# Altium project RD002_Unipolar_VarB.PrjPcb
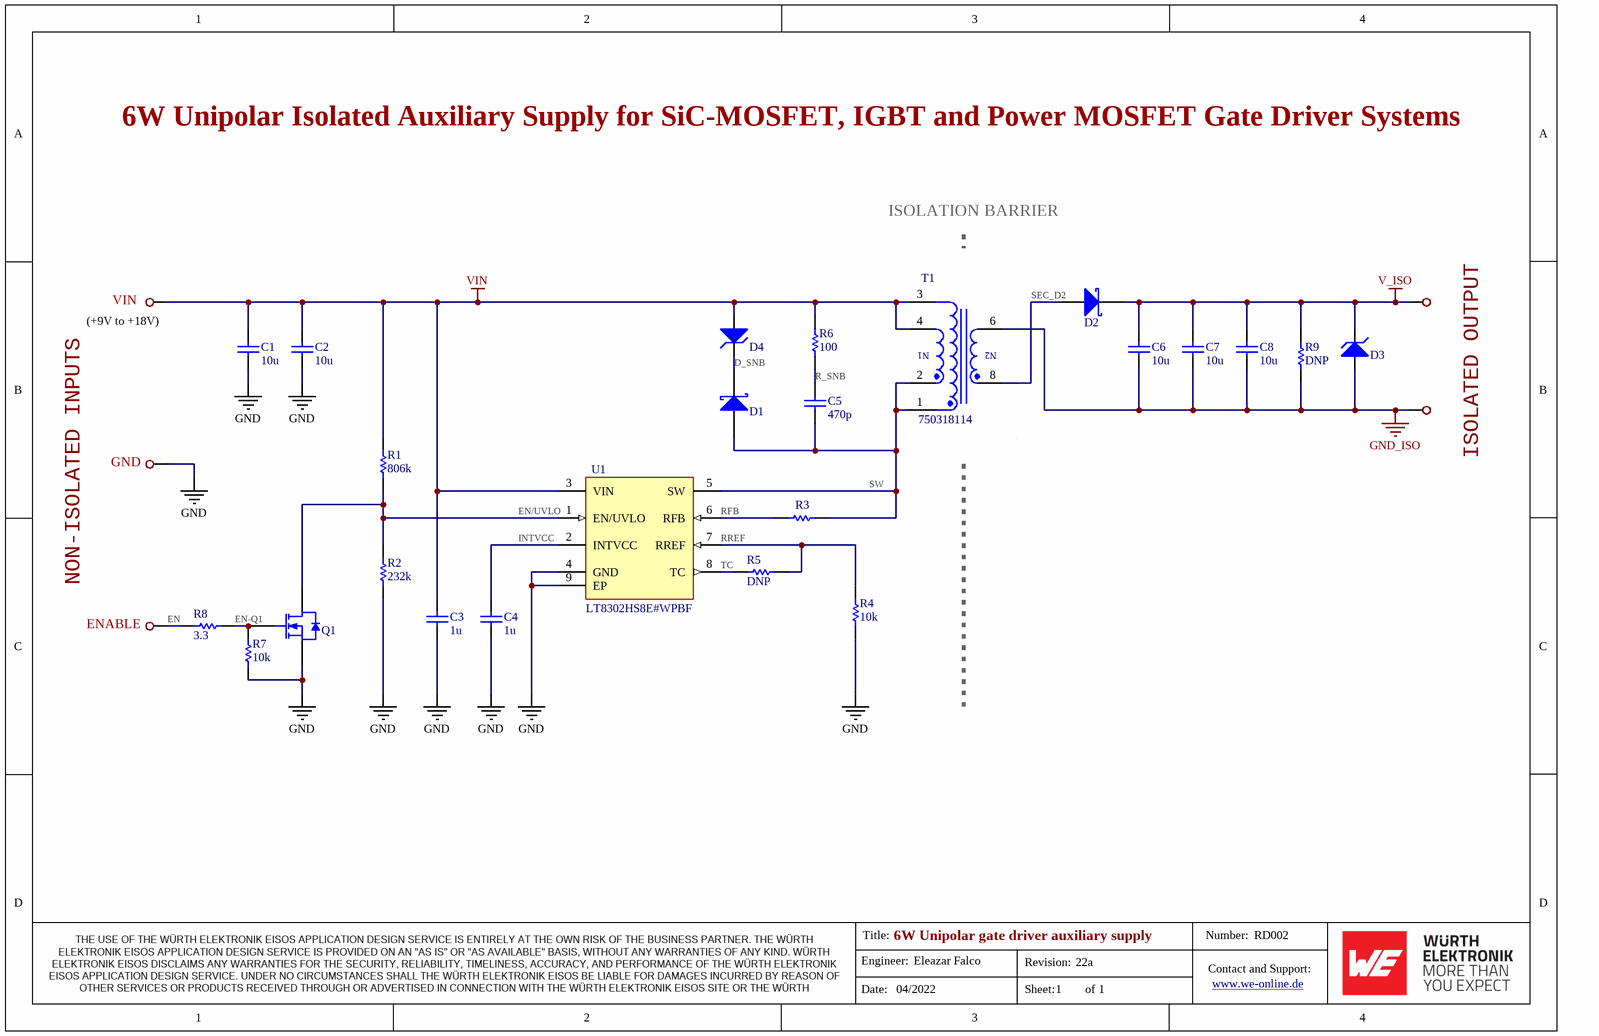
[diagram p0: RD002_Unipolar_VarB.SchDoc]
Board_Name: RD001_VarB; Engineer: Eleazar Falco; Project_Title: Isolated unipolar auxiliary supply for gate driver; Revision: 21a; Variant: N/A; Version: N/A
1 sheet, 29 parts. Net scope: global (net labels, ports and power ports of the same name join across sheets).
Board file: RD002_Unipolar_VarB.PcbDoc

## Sheet RD002_Unipolar_VarB.SchDoc: 6W Unipolar gate driver auxiliary supply
size A4; Date: 04/2022; Author: Eleazar Falco; DocumentNumber: RD002; Revision: 22a; SheetNumber: 1; SheetTotal: 1

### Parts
C1  value 10u  [C1206]  (hidden comment: 885012108022)
C2  value 10u  [C1206]  (hidden comment: 885012108022)
C3  value 1u  [C0805]  (hidden comment: 885012207103)
C4  value 1u  [C0805]  (hidden comment: 885012207103)
C5  value 470p  [C0805]  (hidden comment: 885012207084)
C6  value 10u  [C1206]  (hidden comment: 885012108022)
C7  value 10u  [C1206]  (hidden comment: 885012108022)
C8  value 10u  [C1206]  (hidden comment: 885012108022)
D1  V1PM10-M3  [D_DO-219AD_(uSMP)]  (value not drawn)
D2  VSSAF3M10-M3  [D_DO-221AC_(SMA_Slim)]  (value not drawn)
D3  PLZ16BG3H  [D_DO-219AC_(uSMF)]  (value not drawn)
D4  BZG03C27-M3  [D_DO-214AC_(SMA)]  (value not drawn)
H1  TH-1MM  [PIN-TH-ROUND-1MM]  (value not drawn)  (no BOM)
H2  TH-1MM  [PIN-TH-ROUND-1MM]  (value not drawn)  (no BOM)
H3  TH-1MM  [PIN-TH-ROUND-1MM]  (value not drawn)  (no BOM)
H4  TH-1MM  [PIN-TH-ROUND-1MM]  (value not drawn)  (no BOM)
H5  TH-1MM  [PIN-TH-ROUND-1MM]  (value not drawn)  (no BOM)
Q1  SQ2318AES-T1_BE3  [IC_SOT23-3_V]  (value not drawn)
R1  value 806k  [R0603]  (hidden comment: RC0603FR-07806KL)
R2  value 232k  [R0603]  (hidden comment: RC0603FR-07232KL)
R3  RT0603FRE0771K5L  [R0603]  (value not drawn)
R4  value 10k  [R0603]  (hidden comment: RT0603BRD0710KL)
R5  value DNP  [R0603_DNP]  (hidden comment: R0603_DNP)
R6  value 100  [R0805]  (hidden comment: CMP0805-FX-1000ELF)
R7  value 10k  [R0603]  (hidden comment: RC0603FR-0710KL)
R8  value 3.3  [R0603]  (hidden comment: RC0603FR-073R3L)
R9  value DNP  [R0603_DNP]  (hidden comment: R0603_DNP)
T1  750318114  [EP7_Extended_Rail]
U1  LT8302HS8E#WPBF  [LT-S8E-8_V]

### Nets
GND: C1.2 C2.1 C3.1 C4.1 H2.1 Q1.2(S) R2.1 R4.1 R7.1 U1.4(GND) U1.9(EP)
GND_ISO: C6.1 C7.1 C8.1 D3.A H5.1 R9.1 T1.6
V_ISO: C6.2 C7.2 C8.2 D2.C D3.C H4.1 R9.2
VIN: C1.1 C2.2 C3.2 D4.A H1.1 R1.2 R6.2 T1.3 T1.4 U1.3(VIN)
D_SNB: D1.C D4.C
EN: H3.1 R8.1
EN-Q1: Q1.1(G) R7.2 R8.2
EN/UVLO: Q1.3(D) R1.1 R2.2 U1.1(EN/UVLO)
INTVCC: C4.2 U1.2(INTVCC)
R_SNB: C5.2 R6.1
RFB: R3.1 U1.6(RFB)
RREF: R4.2 R5.2 U1.7(RREF)
SEC_D2: D2.A T1.8
SW: C5.1 D1.A R3.2 T1.1 T1.2 U1.5(SW)
TC: R5.1 U1.8(TC)

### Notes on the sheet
- 6W Unipolar Isolated Auxiliary Supply for SiC-MOSFET, IGBT and Power MOSFET Gate Driver Systems
- ISOLATION BARRIER
- (near H1) VIN
- (near H1) (+9V to +18V)
- (near H2) GND
- ISOLATED OUTPUT
- NON-ISOLATED INPUTS
- (near H3) ENABLE
- Engineer:
- Title:
- Revision:
- Number:
- Contact and Support:
- www.we-online.de <http://www.we-online.de>
- THE USE OF THE WÜRTH ELEKTRONIK EISOS APPLICATION DESIGN SERVICE IS ENTIRELY AT THE OWN RISK OF THE BUSINESS PARTNER. THE WÜRTH ELEKTRONIK EISOS APPLICATION DESIGN SERVICE IS PROVIDED ON AN "AS IS" OR "AS AVAILABLE" BASIS, WITHOUT ANY WARRANTIES OF ANY KIND. WÜRTH ELEKTRONIK EISOS DISCLAIMS ANY WARRANTIES FOR THE SECURITY, RELIABILITY, TIMELINESS, ACCURACY, AND PERFORMANCE OF THE WÜRTH ELEKTRONIK EISOS APPLICATION DESIGN SERVICE. UNDER NO CIRCUMSTANCES SHALL THE WÜRTH ELEKTRONIK EISOS BE LIABLE FOR DAMAGES INCURRED BY REASON OF OTHER SERVICES OR PRODUCTS RECEIVED THROUGH OR ADVERTISED IN CONNECTION WITH THE WÜRTH ELEKTRONIK EISOS SITE OR THE WÜRTH ELEKTRONIK EISOS APPLICATION DESIGN SERVICE.
- Date:
- Sheet:
- of

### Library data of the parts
C1 C2 C6-C8 = 885012108022: MLCC 10uF 50V 10% X7R 1206 General Purpose; MFR: Wurth Elektronik
C3 C4 = 885012207103: MLCC 1uF 50V 10% X7R 0805 General Purpose; MFR: Wurth Elektronik
C5 = 885012207084: MLCC SMD 470p 50V 10% X7R 0805 General Purpose; MFR: Wurth Elektronik
D1 = V1PM10-M3: Schottky Rectifier 1A 100V SMD DO-219AD (uSMP) V1PM10-M3; MFR: Vishay
D2 = VSSAF3M10-M3: Schottky Rectifier 3A 100V SMD DO-221AC (SMA_Slim) VSSAF3M10-M3; MFR: Vishay; Type: Schottky Barrier Rectifier Trench-MOS
D3 = PLZ16BG3H: Zener 16V 0.5W SMD DO-219AC (uSMF) PLZ16BG3H; MFR: Vishay
D4 = BZG03C27-M3: Zener 27V 3W DO-214AC (SMA) BZG03C27-M3; MFR: Vishay
H1-H5 = Pin_hole_1mm: not available; SymbolName_1: TEST-POINT-ROUND; DeviceName: TH-Hole; DeviceSetName: TEST-PIN-TH-1MM; Art.-Code: Pin-hole-1mm
Q1 = SQ2318AES-T1_BE3: N-Channel MOSFET 40 V SOT23-3; MFR: Vishay
R1 = RC0603FR-07806KL: Thick Film Resistors 806k 1% 0.1W; MFR: Yageo; Case-Metric: 1608; Case-EIA: 0603
R2 = RC0603FR-07232KL: Thick Film Resistors 232k 1% 0.1W; MFR: Yageo; Case-Metric: 1608; Case-EIA: 0603
R3 = RT0603FRE0771K5L: Thin Film Resistors 71.5k 0.1% 0.1W 0603 RT0603FRE0771K5L; MFR: Yageo; Case-Metric: 1608; Case-EIA: 0603
R4 = RT0603BRD0710KL: Thin Film Resistors 10k 0.1% 0.1W; MFR: Yageo; Case-Metric: 1608; Case-EIA: 0603
R5 R9 = R0603_DNP: Footprint R0603 DNP
R6 = CMP0805-FX-1000ELF: Thick Film 100 5% 0.5W 0805 High Power CMP0805-FX-1000ELF; MFR: Bourns; Case-EIA: 0805
R7 = RC0603FR-0710KL: Thick Film Resistors 10k 1% 0.1W; MFR: Yageo; Case-Metric: 1608; Case-EIA: 0603
R8 = RC0603FR-073R3L: Thick Film Resistors 3.3 1% 0.1W; MFR: Yageo; Case-Metric: 1608; Case-EIA: 0603
T1 = 750318114: WE-AGDT Auxiliary Gate Drive Transformer, EP7, SMT, 9-18Vin, 19Vout, 6W; MFR: Wurth Elektronik; IC Reference: LT8302; Input Voltage: 9-18V; Interwinding Capacitance: 6.8pF; Output Voltage: 19V; Switching Frequency: 350kHz
U1 = LT8302HS8E#WPBF: Micropower No-Opto Isolated Flyback Converter, 2.8 to 42 V, -40 to 150 degC, 8-Pin SOIC (S8E), RoHS, AEC-Q100; PartNumber: LT8302; MFR: Analog Devices / Linear Tech; Output Current: 3.6 A; Packing: Tube; Number of Outputs: 1; VIN Min: 2.8 V; VIN Max: 42 V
